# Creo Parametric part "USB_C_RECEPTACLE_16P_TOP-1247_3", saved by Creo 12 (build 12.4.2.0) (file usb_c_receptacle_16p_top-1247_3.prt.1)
Units: Custom; MM, KILOGRAM, SECS

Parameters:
  PTC_WM_ITERATION = "0"
  PTC_WM_VERSION = "-.0"
  PTC_WM_LIFECYCLE_STATE = "In Work"
  PTC_WM_LIFECYCLE = "MO_CADDocument"
  PTC_WM_CREATED_BY = "Maximilian Roepper (Z0017RMS: MO)"
  PTC_WM_CREATED_ON = "18-Sep-26 11:36:42 AM"
  PTC_WM_MODIFIED_BY = "Maximilian Roepper (Z0017RMS: MO)"
  PTC_WM_MODIFIED_ON = "18-Sep-26 11:36:46 AM"
  PDMLINKNUMBER = "PDM000071454799"
  PTC_WM_NAME = "usb_c_receptacle_16p_top-1247_3.prt"
  PTC_WM_NUMBER = "PDM000071454799"

Other parameters: WEIGHT, WEIGHT_FACTOR, WEIGHT_ADD, _MASS_TEMP, _DIFF_TEMP, MC_ERRORS, SUPPLIER

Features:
  1. coordinate system
  2. datum plane "PRT_YZ"
  3. datum plane "PRT_XY"
  4. datum plane "PRT_XZ"
  5. coordinate system
  6. datum axis
  7. datum axis
  8. datum axis
  9. coordinate system
  10. imported feature
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
Other named items: PRT, SIEMENS_MO, DRW_VIEW_ORG, PRT_X, PRT_Y, PRT_Z, CS0, ROUGH_GROB

Layers: 00_STD_CSYS-KSYS, 01_STD_PLANES-EBENEN, 02_STD_AXES-ACHSEN, 03_STD_CSYS-KSYS, 24_IMPORT_FEAT-IMPORT_KE

Surfaces: 6 plane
